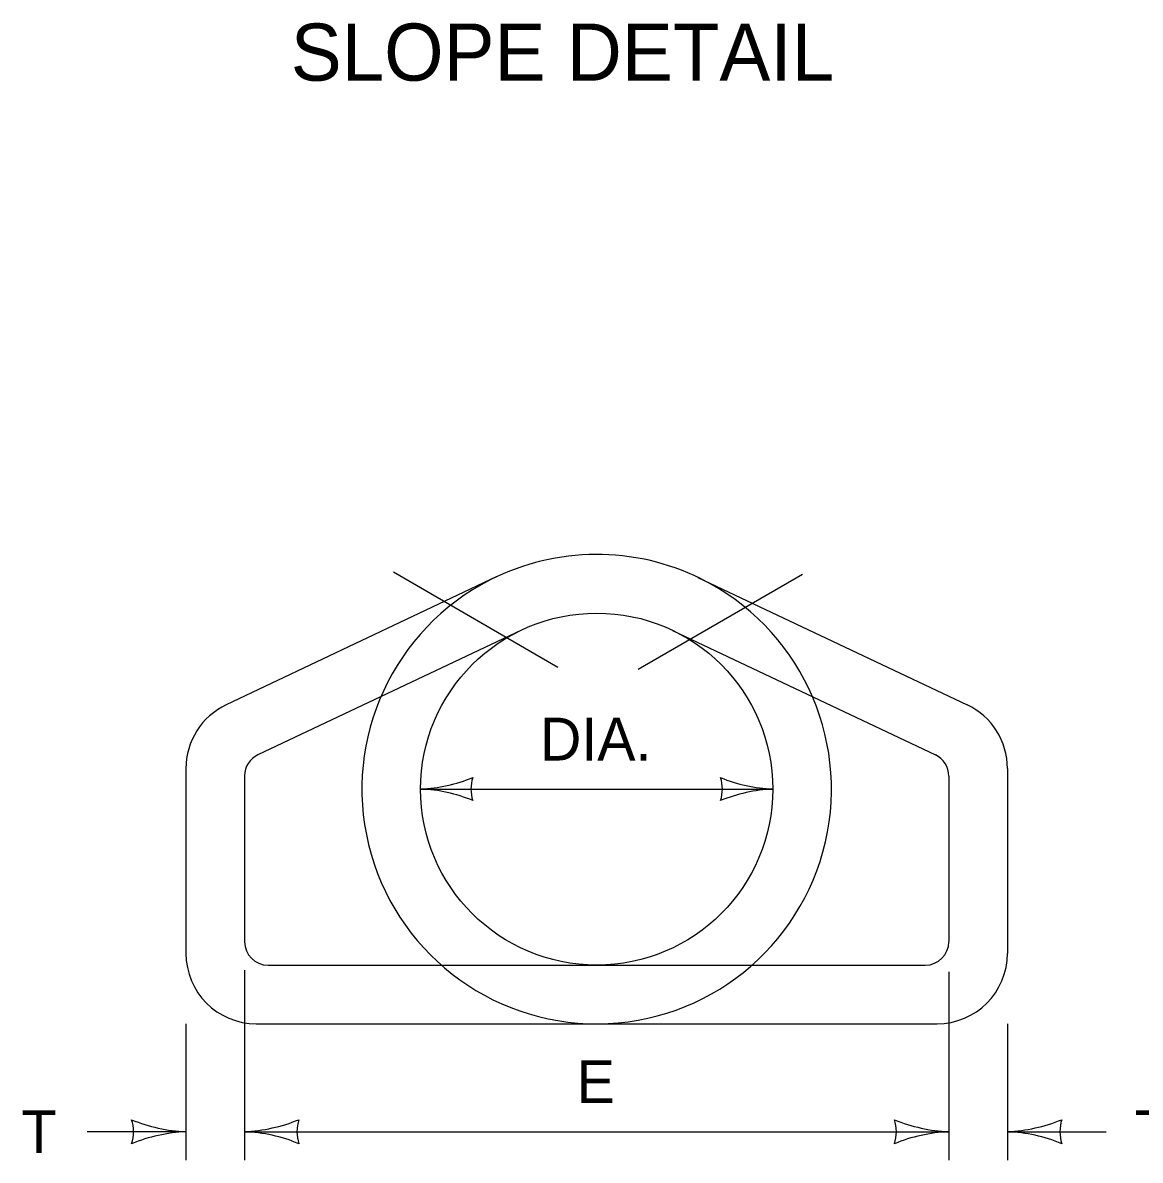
# Model space of a CAD drawing. Extents: x 49991.4 to 50022.1, y 49985 to 50011.4.
# Drawn here: x 50013.605 to 50015.17, y 49995.209 to 49996.802 of the extents above; entities that cross this region are included whole.
import ezdxf

# ---------------------------------------------------------------- set-up
doc = ezdxf.new("R2010")
doc.units = 0
for name, color, linetype in [('Level 1', 7, 'Continuous'), ('Level 2', 7, 'Continuous'), ('Level 3', 7, 'Continuous'), ('Level 4', 7, 'Continuous'), ('Level 5', 7, 'Continuous')]:
    doc.layers.add(name, color=color, linetype=linetype)

msp = doc.modelspace()

# ---------------------------------------------------------------- linework, layer by layer
at = {"layer": 'Level 1'}
for p, q in [((50014.2677, 49996.0258), (50013.8895, 49995.8466)), ((50014.5503, 49996.0252), (50014.9274, 49995.8466)), ((50014.303, 49995.9514), (50013.934, 49995.7767)), ((50014.5147, 49995.9507), (50014.8828, 49995.7765)), ((50013.8331, 49995.7574), (50013.8331, 49995.4984)), ((50014.9837, 49995.7574), (50014.9837, 49995.4984)), ((50013.9152, 49995.747), (50013.9152, 49995.5149)), ((50014.9015, 49995.7467), (50014.9015, 49995.5149)), ((50013.9482, 49995.482), (50014.8687, 49995.482)), ((50013.9317, 49995.3998), (50014.8851, 49995.3998))]:
    msp.add_line(p, q, dxfattribs=at)
msp.add_circle((50014.4084, 49995.7285), 0.2466, dxfattribs=at)
for centre, radius, start, end in [((50014.4084, 49995.7285), 0.3288, 63.781, 116.8033), ((50013.9317, 49995.7574), 0.0986, 115.3382, 180), ((50014.8851, 49995.7574), 0.0986, 0, 64.6616), ((50013.9481, 49995.747), 0.0329, 115.3436, 180), ((50014.8687, 49995.7467), 0.0329, 0, 64.6714), ((50013.9481, 49995.5148), 0.0329, 180, 270), ((50014.8687, 49995.5148), 0.0329, 270, 0), ((50013.9317, 49995.4984), 0.0986, 180, 270), ((50014.8851, 49995.4984), 0.0986, 270, 0)]:
    msp.add_arc(centre, radius, start, end, dxfattribs=at)
at = {"layer": 'Level 3'}
for p, q in [((50014.1618, 49995.7286), (50014.655, 49995.7286)), ((50013.9152, 49995.4749), (50013.9152, 49995.2086)), ((50014.9015, 49995.4727), (50014.9015, 49995.2086)), ((50013.8331, 49995.3998), (50013.8331, 49995.2086)), ((50014.9838, 49995.3998), (50014.9838, 49995.2086)), ((50013.8331, 49995.2486), (50013.6948, 49995.2486)), ((50013.9152, 49995.2486), (50014.9015, 49995.2486)), ((50014.9838, 49995.2486), (50015.1221, 49995.2486))]:
    msp.add_line(p, q, dxfattribs=at)
for centre, radius, start, end in [((50014.1508, 49995.952), 0.2237, 272.8273, 292.0772), ((50014.2849, 49995.7286), 0.0526, 162.1388, 197.8612), ((50014.6638, 49995.9418), 0.2134, 247.456, 267.6395), ((50014.5319, 49995.7286), 0.0526, 342.1388, 17.8612), ((50014.1531, 49995.5154), 0.2134, 67.456, 87.6395), ((50014.666, 49995.5052), 0.2237, 92.8273, 112.0772), ((50013.8423, 49995.4707), 0.2223, 247.456, 267.6395), ((50013.7049, 49995.2486), 0.0548, 342.1388, 17.8612), ((50013.9037, 49995.4813), 0.233, 272.8273, 292.0772), ((50014.0434, 49995.2486), 0.0548, 162.1388, 197.8612), ((50014.9107, 49995.4707), 0.2223, 247.456, 267.6395), ((50014.7733, 49995.2486), 0.0548, 342.1388, 17.8612), ((50014.9723, 49995.4813), 0.233, 272.8273, 292.0772), ((50015.112, 49995.2486), 0.0548, 162.1388, 197.8612), ((50013.8446, 49995.0159), 0.233, 92.8273, 112.0772), ((50013.906, 49995.0265), 0.2223, 67.456, 87.6395), ((50014.913, 49995.0159), 0.233, 92.8273, 112.0772), ((50014.9746, 49995.0265), 0.2223, 67.456, 87.6395)]:
    msp.add_arc(centre, radius, start, end, dxfattribs=at)
at = {"layer": 'Level 4'}
msp.add_arc((50014.4084, 49995.7285), 0.3288, 116.9522, 63.6963, dxfattribs=at)
at = {"layer": 'Level 5'}
for p, q in [((50014.354, 49995.899), (50014.1236, 49996.0323)), ((50014.4663, 49995.8967), (50014.6968, 49996.0296))]:
    msp.add_line(p, q, dxfattribs=at)

# ---------------------------------------------------------------- texts
at = {"layer": 'Level 2'}
for s, height, p in [('SLOPE DETAIL', 0.08, (50013.9799, 49996.721)), ('DIA.', 0.06, (50014.329, 49995.7686)), ('E', 0.06, (50014.3804, 49995.2886)), ('T', 0.06, (50013.6028, 49995.2186)), ('T', 0.06, (50015.1621, 49995.2186))]:
    msp.add_text(s, height=height, dxfattribs=at).set_placement(p)

doc.saveas('drawing.dxf')
